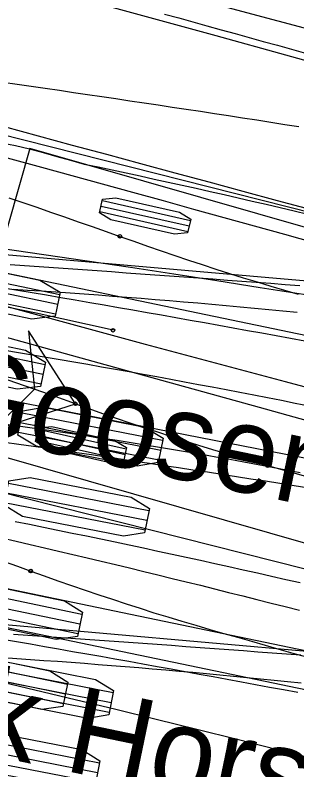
# Model space of a CAD drawing. Extents: x -14 to 1565148, y -25 to 642856.
# Drawn here: x 1565038.13 to 1565044.63, y 636508.4 to 636525.81 of the extents above; entities that cross this region are included whole.
import ezdxf

# ---------------------------------------------------------------- set-up
doc = ezdxf.new("R2010")
doc.units = 0
for name, color, linetype in [('DR_P_Headwall', 7, 'Continuous'), ('GE_P_Alignment_100_Stations', 7, 'Continuous'), ('MT_P_Work_Area', 7, 'Continuous'), ('PM_P_Edge_Line', 7, 'Continuous'), ('TR_Turning_Path25', 7, 'Continuous'), ('TR_Turning_Path27', 7, 'Continuous'), ('TR_Turning_Path28', 7, 'Continuous'), ('TR_Turning_Path29', 7, 'Continuous')]:
    doc.layers.add(name, color=color, linetype=linetype)

msp = doc.modelspace()

# ---------------------------------------------------------------- linework, layer by layer
at = {"layer": 'DR_P_Headwall'}
for p, q in [((1565038.469, 636522.731), (1565036.541, 636516.001)), ((1565056.734, 636517.497), (1565038.469, 636522.731)), ((1565040.113, 636521.406), (1565042.145, 636520.948)), ((1565040.142, 636521.533), (1565042.174, 636521.075)), ((1565040.085, 636521.279), (1565042.117, 636520.821)), ((1565038.661, 636516.257), (1565040.694, 636515.802)), ((1565036.541, 636516.001), (1565054.806, 636510.768)), ((1565038.604, 636516.003), (1565040.637, 636515.547)), ((1565038.633, 636516.13), (1565040.666, 636515.674))]:
    msp.add_line(p, q, dxfattribs=at)
for points in [[(1565037.813, 636522.867), (1565038.136, 636522.8), (1565038.458, 636522.727), (1565038.776, 636522.642), (1565039.092, 636522.552), (1565039.408, 636522.462), (1565039.725, 636522.376), (1565040.049, 636522.308), (1565040.372, 636522.239), (1565040.695, 636522.17), (1565041.018, 636522.1), (1565041.341, 636522.029), (1565041.664, 636521.959), (1565041.986, 636521.887), (1565042.309, 636521.816), (1565042.631, 636521.743), (1565042.954, 636521.67), (1565043.276, 636521.597), (1565043.598, 636521.523), (1565043.92, 636521.449), (1565044.242, 636521.374), (1565044.564, 636521.299), (1565044.885, 636521.223)], [(1565044.703, 636512.71), (1565044.375, 636512.785), (1565044.047, 636512.86), (1565043.719, 636512.934), (1565043.391, 636513.007), (1565043.063, 636513.08), (1565042.735, 636513.153), (1565042.406, 636513.225), (1565042.078, 636513.297), (1565041.749, 636513.368), (1565041.421, 636513.439), (1565041.092, 636513.509), (1565040.763, 636513.579), (1565040.434, 636513.649), (1565040.105, 636513.718), (1565039.776, 636513.786), (1565039.446, 636513.854), (1565039.117, 636513.922), (1565038.787, 636513.989), (1565038.458, 636514.056), (1565038.128, 636514.122)]]:
    msp.add_lwpolyline(points, dxfattribs=at)
for points in [[(1565040.077, 636521.248), (1565040.149, 636521.565), (1565040.455, 636521.596), (1565041.918, 636521.266), (1565042.181, 636521.106), (1565042.11, 636520.789), (1565041.804, 636520.758), (1565040.34, 636521.088)], [(1565038.597, 636515.971), (1565038.668, 636516.289), (1565038.974, 636516.32), (1565040.438, 636515.992), (1565040.701, 636515.833), (1565040.63, 636515.516), (1565040.324, 636515.484), (1565038.861, 636515.812)]]:
    msp.add_lwpolyline(points, close=True, dxfattribs=at)
msp.add_circle((1565040.389, 636518.54), 0.0417, dxfattribs=at)
msp.add_arc((1564998.655, 636332.944), 190.231, 77.32682, 100.64576, dxfattribs=at)
at = {"layer": 'GE_P_Alignment_100_Stations'}
for points in [[(1565055.623, 636521.727), (1565052.405, 636522.645), (1565049.196, 636523.548), (1565045.984, 636524.445), (1565042.771, 636525.336), (1565039.555, 636526.219), (1565036.338, 636527.097), (1565033.119, 636527.967), (1565029.898, 636528.831), (1565026.676, 636529.688), (1565023.452, 636530.538), (1565020.225, 636531.382), (1565016.998, 636532.219), (1565013.768, 636533.049), (1565010.537, 636533.872), (1565010.214, 636533.954)], [(1565084.916, 636515.464), (1565081.699, 636516.213), (1565078.473, 636516.978), (1565075.25, 636517.751), (1565072.028, 636518.534), (1565068.809, 636519.324), (1565065.591, 636520.124), (1565062.376, 636520.932), (1565059.163, 636521.749), (1565055.952, 636522.574), (1565052.744, 636523.408), (1565049.537, 636524.25), (1565046.333, 636525.101), (1565043.131, 636525.961), (1565039.932, 636526.829), (1565036.735, 636527.706), (1565034.179, 636528.414)], [(1565053.339, 636514.06), (1565050.158, 636514.967), (1565046.964, 636515.866), (1565043.768, 636516.759), (1565040.57, 636517.644), (1565037.371, 636518.524), (1565034.17, 636519.396), (1565030.967, 636520.262), (1565027.762, 636521.121), (1565024.555, 636521.974), (1565021.347, 636522.82), (1565018.137, 636523.659), (1565014.925, 636524.492), (1565011.711, 636525.318), (1565008.496, 636526.137), (1565008.174, 636526.219)], [(1565041.579, 636525.836), (1565041.904, 636525.746), (1565042.23, 636525.656), (1565042.555, 636525.566), (1565042.88, 636525.476), (1565043.205, 636525.386), (1565043.53, 636525.296), (1565043.855, 636525.206), (1565044.18, 636525.116), (1565044.505, 636525.026), (1565044.83, 636524.935)], [(1565083.222, 636507.646), (1565079.958, 636508.405), (1565076.712, 636509.174), (1565073.467, 636509.953), (1565070.225, 636510.74), (1565066.985, 636511.535), (1565063.747, 636512.34), (1565060.511, 636513.153), (1565057.277, 636513.974), (1565054.045, 636514.805), (1565050.816, 636515.644), (1565047.589, 636516.491), (1565044.364, 636517.348), (1565041.141, 636518.213), (1565037.921, 636519.086), (1565034.703, 636519.968), (1565032.131, 636520.68)], [(1565044.912, 636516.791), (1565044.593, 636516.854), (1565044.274, 636516.917), (1565043.955, 636516.98), (1565043.636, 636517.042), (1565043.316, 636517.103), (1565042.997, 636517.164), (1565042.678, 636517.225), (1565042.359, 636517.285), (1565042.04, 636517.345), (1565041.721, 636517.404), (1565041.402, 636517.463), (1565041.083, 636517.521), (1565040.763, 636517.579), (1565040.444, 636517.636), (1565040.125, 636517.692), (1565039.806, 636517.749), (1565039.487, 636517.804), (1565039.167, 636517.859), (1565038.848, 636517.913), (1565038.529, 636517.967), (1565038.21, 636518.02), (1565037.89, 636518.073)], [(1565044.706, 636515.25), (1565044.381, 636515.312), (1565044.057, 636515.374), (1565043.733, 636515.435), (1565043.408, 636515.495), (1565043.084, 636515.555), (1565042.759, 636515.613), (1565042.434, 636515.67), (1565042.109, 636515.727), (1565041.784, 636515.782), (1565041.458, 636515.837), (1565041.133, 636515.891), (1565040.807, 636515.943), (1565040.481, 636515.995), (1565040.156, 636516.046), (1565039.83, 636516.096), (1565039.503, 636516.144), (1565039.177, 636516.192), (1565038.851, 636516.238), (1565038.524, 636516.284), (1565038.197, 636516.329), (1565037.87, 636516.372)]]:
    msp.add_lwpolyline(points, dxfattribs=at)
for centre, radius, start, end in [((1564614.651, 634973.928), 1605.395, 74.111231, 75.773222), ((1565365.694, 637720.982), 1241.789, 254.467176, 256.876425)]:
    msp.add_arc(centre, radius, start, end, dxfattribs=at)
at = {"layer": 'MT_P_Work_Area'}
for p, q in [((1565035.569, 636520.113), (1565039.159, 636519.366)), ((1565035.522, 636519.888), (1565039.112, 636519.142)), ((1565072.656, 636512.633), (1565037.41, 636519.964)), ((1565035.476, 636519.664), (1565039.065, 636518.917)), ((1565035.233, 636518.497), (1565038.823, 636517.751)), ((1565035.186, 636518.273), (1565038.776, 636517.526)), ((1565035.14, 636518.049), (1565038.729, 636517.302)), ((1565035.781, 636512.131), (1565071.027, 636504.801))]:
    msp.add_line(p, q, dxfattribs=at)
for points in [[(1565035.464, 636519.608), (1565035.58, 636520.168), (1565036.118, 636520.233), (1565038.703, 636519.695), (1565039.17, 636519.422), (1565039.054, 636518.862), (1565038.516, 636518.798), (1565035.931, 636519.335)], [(1565035.128, 636517.993), (1565035.244, 636518.553), (1565035.782, 636518.617), (1565038.367, 636518.08), (1565038.834, 636517.806), (1565038.718, 636517.246), (1565038.18, 636517.182), (1565035.595, 636517.72)]]:
    msp.add_lwpolyline(points, close=True, dxfattribs=at)
for points in [[(1565044.811, 636518.287), (1565044.481, 636518.348), (1565044.151, 636518.409), (1565043.82, 636518.47), (1565043.49, 636518.53), (1565043.159, 636518.59), (1565042.829, 636518.65), (1565042.498, 636518.71), (1565042.167, 636518.769), (1565041.836, 636518.828), (1565041.505, 636518.887), (1565041.174, 636518.945), (1565040.843, 636519.003), (1565040.512, 636519.061), (1565040.181, 636519.119), (1565039.85, 636519.176), (1565039.518, 636519.234), (1565039.187, 636519.29), (1565038.856, 636519.347), (1565038.524, 636519.403), (1565038.192, 636519.459), (1565037.861, 636519.515)], [(1565044.648, 636510.179), (1565044.323, 636510.24), (1565043.999, 636510.301), (1565043.674, 636510.361), (1565043.35, 636510.422), (1565043.025, 636510.482), (1565042.701, 636510.541), (1565042.377, 636510.601), (1565042.052, 636510.66), (1565041.728, 636510.719), (1565041.403, 636510.778), (1565041.079, 636510.836), (1565040.755, 636510.895), (1565040.43, 636510.952), (1565040.106, 636511.01), (1565039.782, 636511.067), (1565039.457, 636511.124), (1565039.133, 636511.181), (1565038.808, 636511.238), (1565038.484, 636511.294), (1565038.16, 636511.35), (1565037.835, 636511.405)]]:
    msp.add_lwpolyline(points, dxfattribs=at)
at = {"layer": 'PM_P_Edge_Line'}
for points in [[(1565037.849, 636524.264), (1565038.174, 636524.217), (1565038.5, 636524.171), (1565038.825, 636524.124), (1565039.151, 636524.077), (1565039.476, 636524.029), (1565039.801, 636523.982), (1565040.127, 636523.934), (1565040.452, 636523.886), (1565040.777, 636523.838), (1565041.103, 636523.789), (1565041.428, 636523.741), (1565041.753, 636523.692), (1565042.078, 636523.642), (1565042.403, 636523.593), (1565042.728, 636523.543), (1565043.053, 636523.494), (1565043.378, 636523.443), (1565043.703, 636523.393), (1565044.028, 636523.343), (1565044.353, 636523.292), (1565044.678, 636523.241)], [(1565044.904, 636514.9), (1565044.57, 636514.952), (1565044.236, 636515.005), (1565043.902, 636515.057), (1565043.568, 636515.108), (1565043.234, 636515.16), (1565042.9, 636515.211), (1565042.566, 636515.263), (1565042.232, 636515.313), (1565041.898, 636515.364), (1565041.563, 636515.415), (1565041.229, 636515.465), (1565040.895, 636515.515), (1565040.561, 636515.565), (1565040.226, 636515.614), (1565039.892, 636515.663), (1565039.557, 636515.712), (1565039.223, 636515.761), (1565038.888, 636515.81), (1565038.554, 636515.858), (1565038.219, 636515.906), (1565037.885, 636515.954)]]:
    msp.add_lwpolyline(points, dxfattribs=at)
msp.add_arc((1564974.513, 636082.407), 442.57, 79.68783, 88.0519, dxfattribs=at)
at = {"layer": 'TR_Turning_Path25'}
for p, q in [((1565061.6, 636507.657), (1565026.354, 636514.984)), ((1565039.671, 636511.982), (1565036.441, 636512.653)), ((1565039.625, 636511.757), (1565036.394, 636512.429)), ((1565039.578, 636511.533), (1565036.347, 636512.205)), ((1565039.336, 636510.366), (1565036.105, 636511.038)), ((1565039.289, 636510.142), (1565036.058, 636510.813)), ((1565039.242, 636509.917), (1565036.011, 636510.589))]:
    msp.add_line(p, q, dxfattribs=at)
msp.add_lwpolyline([(1565037.824, 636513.752), (1565038.151, 636513.676), (1565038.479, 636513.599), (1565038.806, 636513.523), (1565039.134, 636513.446), (1565039.461, 636513.368), (1565039.788, 636513.29), (1565040.116, 636513.212), (1565040.443, 636513.134), (1565040.77, 636513.055), (1565041.097, 636512.976), (1565041.423, 636512.896), (1565041.75, 636512.816), (1565042.077, 636512.736), (1565042.404, 636512.655), (1565042.73, 636512.574), (1565043.056, 636512.493), (1565043.383, 636512.411), (1565043.709, 636512.329), (1565044.035, 636512.247), (1565044.361, 636512.164), (1565044.687, 636512.081)], dxfattribs=at)
for points in [[(1565039.683, 636512.037), (1565039.567, 636511.477), (1565039.079, 636511.403), (1565036.753, 636511.886), (1565036.336, 636512.149), (1565036.452, 636512.709), (1565036.94, 636512.784), (1565039.266, 636512.3)], [(1565039.347, 636510.422), (1565039.231, 636509.862), (1565038.743, 636509.787), (1565036.417, 636510.271), (1565036, 636510.533), (1565036.116, 636511.093), (1565036.604, 636511.168), (1565038.93, 636510.685)]]:
    msp.add_lwpolyline(points, close=True, dxfattribs=at)
msp.add_arc((1564967.411, 636209.604), 308.945, 69.72175, 81.14322, dxfattribs=at)
at = {"layer": 'TR_Turning_Path27'}
for p, q in [((1565080.683, 636508.555), (1565033.648, 636517.772)), ((1565041.532, 636515.993), (1565038.294, 636516.628)), ((1565041.488, 636515.768), (1565038.25, 636516.403)), ((1565041.444, 636515.543), (1565038.206, 636516.178)), ((1565041.215, 636514.374), (1565037.977, 636515.008)), ((1565041.171, 636514.149), (1565037.932, 636514.784)), ((1565041.127, 636513.924), (1565037.888, 636514.559)), ((1565040.391, 636510.171), (1565037.153, 636510.805)), ((1565040.347, 636509.946), (1565037.109, 636510.58)), ((1565040.303, 636509.721), (1565037.065, 636510.355)), ((1565040.074, 636508.551), (1565036.836, 636509.186)), ((1565040.03, 636508.326), (1565036.792, 636508.961)), ((1565039.986, 636508.102), (1565036.747, 636508.736))]:
    msp.add_line(p, q, dxfattribs=at)
for points in [[(1565037.985, 636521.598), (1565038.306, 636521.488), (1565038.627, 636521.378), (1565038.948, 636521.268), (1565039.268, 636521.157), (1565039.588, 636521.045), (1565039.908, 636520.933), (1565040.228, 636520.82), (1565040.548, 636520.707)], [(1565040.547, 636520.707), (1565040.865, 636520.594), (1565041.181, 636520.483), (1565041.497, 636520.374), (1565041.813, 636520.266), (1565042.128, 636520.16), (1565042.445, 636520.056), (1565042.761, 636519.953), (1565043.077, 636519.852), (1565043.393, 636519.752), (1565043.71, 636519.655), (1565044.026, 636519.559), (1565044.343, 636519.465), (1565044.66, 636519.373)], [(1565039.52, 636516.845), (1565038.435, 636518.525), (1565038.578, 636517.181), (1565037.617, 636516.232), (1565039.52, 636516.845)], [(1565039.52, 636516.845), (1565039.834, 636516.733), (1565040.148, 636516.622), (1565040.463, 636516.513), (1565040.778, 636516.405), (1565041.094, 636516.298), (1565041.411, 636516.193), (1565041.728, 636516.09), (1565042.045, 636515.988), (1565042.363, 636515.888), (1565042.682, 636515.79), (1565043.001, 636515.693), (1565043.32, 636515.599), (1565043.64, 636515.506), (1565043.961, 636515.414)], [(1565037.878, 636513.203), (1565038.184, 636513.094), (1565038.489, 636512.985)], [(1565038.49, 636512.984), (1565038.8, 636512.873), (1565039.113, 636512.762), (1565039.427, 636512.652), (1565039.742, 636512.544), (1565040.059, 636512.437), (1565040.376, 636512.332), (1565040.693, 636512.228), (1565041.012, 636512.125), (1565041.332, 636512.024), (1565041.653, 636511.925), (1565041.975, 636511.828), (1565042.297, 636511.732), (1565042.621, 636511.638), (1565042.943, 636511.546), (1565043.262, 636511.456), (1565043.58, 636511.365), (1565043.899, 636511.275), (1565044.217, 636511.184), (1565044.536, 636511.093), (1565044.854, 636511.002)]]:
    msp.add_lwpolyline(points, dxfattribs=at)
for points in [[(1565039.52, 636516.845), (1565038.435, 636518.525), (1565038.578, 636517.181), (1565037.617, 636516.232)], [(1565041.543, 636516.049), (1565041.433, 636515.488), (1565040.947, 636515.407), (1565038.615, 636515.864), (1565038.195, 636516.122), (1565038.305, 636516.683), (1565038.791, 636516.764), (1565041.123, 636516.307)], [(1565041.226, 636514.43), (1565041.116, 636513.868), (1565040.629, 636513.788), (1565038.298, 636514.245), (1565037.877, 636514.503), (1565037.987, 636515.064), (1565038.474, 636515.145), (1565040.806, 636514.688)], [(1565040.402, 636510.226), (1565040.292, 636509.665), (1565039.806, 636509.585), (1565037.474, 636510.042), (1565037.054, 636510.3), (1565037.164, 636510.861), (1565037.65, 636510.941), (1565039.982, 636510.484)], [(1565040.085, 636508.607), (1565039.975, 636508.046), (1565039.488, 636507.965), (1565037.157, 636508.422), (1565036.737, 636508.68), (1565036.847, 636509.242), (1565037.333, 636509.322), (1565039.665, 636508.865)]]:
    msp.add_lwpolyline(points, close=True, dxfattribs=at)
for centre in [(1565040.547, 636520.707), (1565040.548, 636520.707), (1565039.52, 636516.845), (1565039.52, 636516.845), (1565043.961, 636515.414), (1565043.961, 636515.414), (1565038.489, 636512.985), (1565038.49, 636512.984)]:
    msp.add_circle(centre, 0.0417, dxfattribs=at)
for centre, radius, start, end in [((1564977.942, 636344.712), 182.816, 70.31624, 80.19793), ((1564828.253, 635754.783), 790.626, 70.211484, 74.167159)]:
    msp.add_arc(centre, radius, start, end, dxfattribs=at)
at = {"layer": 'TR_Turning_Path28'}
for p, q in [((1565076.765, 636516.872), (1565029.02, 636521.062)), ((1565028.277, 636512.594), (1565076.022, 636508.405))]:
    msp.add_line(p, q, dxfattribs=at)
for points in [[(1565044.696, 636519.567), (1565044.362, 636519.592), (1565044.028, 636519.617), (1565043.694, 636519.642), (1565043.36, 636519.667), (1565043.026, 636519.691), (1565042.692, 636519.716), (1565042.358, 636519.741), (1565042.024, 636519.765), (1565041.69, 636519.789), (1565041.356, 636519.813), (1565041.022, 636519.837), (1565040.688, 636519.861), (1565040.354, 636519.885), (1565040.02, 636519.909), (1565039.686, 636519.933), (1565039.352, 636519.956), (1565039.018, 636519.98), (1565038.684, 636520.003), (1565038.349, 636520.026), (1565038.015, 636520.049)], [(1565044.721, 636511.041), (1565044.389, 636511.066), (1565044.058, 636511.091), (1565043.726, 636511.116), (1565043.395, 636511.141), (1565043.063, 636511.166), (1565042.732, 636511.19), (1565042.4, 636511.215), (1565042.069, 636511.239), (1565041.737, 636511.263), (1565041.406, 636511.287), (1565041.074, 636511.312), (1565040.743, 636511.336), (1565040.411, 636511.359), (1565040.08, 636511.383), (1565039.748, 636511.407), (1565039.417, 636511.43), (1565039.086, 636511.454), (1565038.754, 636511.477), (1565038.423, 636511.501), (1565038.091, 636511.524)]]:
    msp.add_lwpolyline(points, dxfattribs=at)
at = {"layer": 'TR_Turning_Path29'}
for p, q in [((1565046.78, 636520.791), (1565032.236, 636524.462)), ((1565030.278, 636516.705), (1565044.822, 636513.034))]:
    msp.add_line(p, q, dxfattribs=at)
for points in [[(1565044.634, 636518.951), (1565044.307, 636518.983), (1565043.98, 636519.015), (1565043.652, 636519.046), (1565043.325, 636519.076), (1565042.998, 636519.106), (1565042.671, 636519.135), (1565042.343, 636519.164), (1565042.016, 636519.192), (1565041.689, 636519.219), (1565041.361, 636519.246), (1565041.034, 636519.272), (1565040.707, 636519.298), (1565040.379, 636519.323), (1565040.052, 636519.347), (1565039.724, 636519.371), (1565039.397, 636519.394), (1565039.069, 636519.417), (1565038.742, 636519.439), (1565038.414, 636519.46), (1565038.087, 636519.481)], [(1565044.728, 636510.398), (1565044.415, 636510.431), (1565044.103, 636510.462), (1565043.79, 636510.493), (1565043.478, 636510.524), (1565043.165, 636510.554), (1565042.853, 636510.584), (1565042.541, 636510.613), (1565042.228, 636510.641), (1565041.916, 636510.669), (1565041.604, 636510.696), (1565041.292, 636510.723), (1565040.98, 636510.749), (1565040.667, 636510.774), (1565040.355, 636510.799), (1565040.043, 636510.824), (1565039.731, 636510.848), (1565039.419, 636510.871), (1565039.107, 636510.894), (1565038.795, 636510.916), (1565038.484, 636510.937), (1565038.172, 636510.958), (1565037.86, 636510.979)]]:
    msp.add_lwpolyline(points, dxfattribs=at)

# ---------------------------------------------------------------- texts
at = {"layer": 'MT_P_Work_Area'}
msp.add_text('Gooseneck Horse Trailer', height=2, rotation=348.2502, dxfattribs=at).set_placement((1565036.302, 636516.272))
at = {"layer": 'TR_Turning_Path25'}
msp.add_text('Gooseneck Horse Trailer', height=2, rotation=348.2571, dxfattribs=at).set_placement((1565025.246, 636511.292))

doc.saveas('drawing.dxf')
